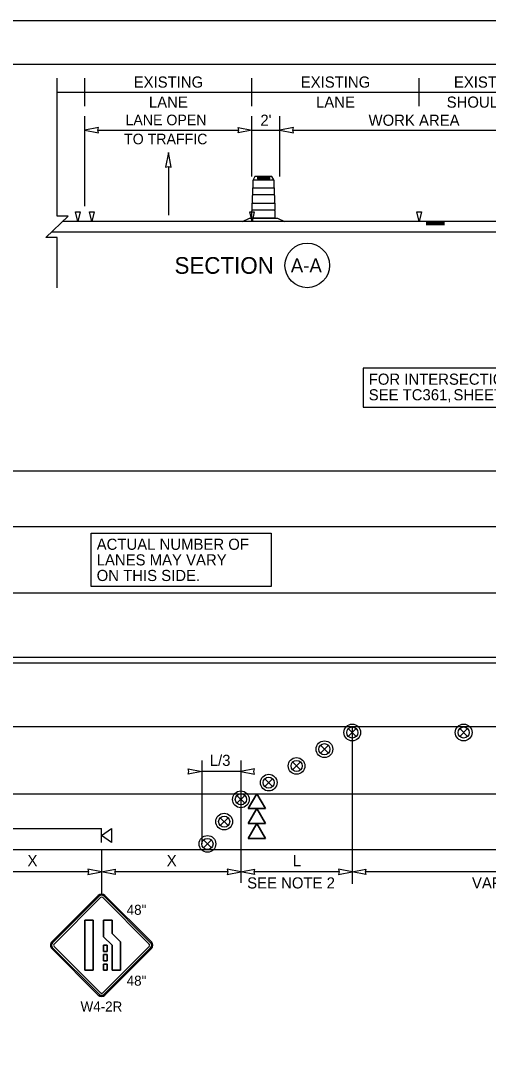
# Model space of a CAD drawing. Extents: x 99958 to 100176, y 99935 to 100011.
# Drawn here: x 100004.18 to 100007.54, y 100003.24 to 100010.69 of the extents above; entities that cross this region are included whole.
import ezdxf

# ---------------------------------------------------------------- set-up
doc = ezdxf.new("R2010")
doc.units = 0
for name, color, linetype in [('RD_ED_ShoulderPavedEdge', 7, 'Continuous'), ('RD_MK_LineDblYellowCenter', 7, 'Continuous'), ('RD_MK_LineEdgeWhite', 7, 'Continuous'), ('RD_MK_LineLane', 7, 'Continuous'), ('SH_GI_PlotLimits', 7, 'Continuous'), ('SH_GI_SheetBorder', 7, 'Continuous'), ('SH_TI_Tables', 7, 'Continuous'), ('SH_TI_WZSectionCut', 7, 'Continuous'), ('TR_SN_ConstructionSigns', 7, 'Continuous'), ('TR_WZ_ArrowLeftStrRightTurn', 7, 'Continuous'), ('TR_WZ_PortableSignMountBlk-Org', 7, 'Continuous'), ('TR_WZ_SequentialArrowSign', 7, 'Continuous'), ('TR_WZ_TrafficSafetyDrum', 7, 'Continuous'), ('TR_WZ_TrafficSafetyDrumElev', 7, 'Continuous'), ('TR_WZ_WorkZoneDetails', 7, 'Continuous'), ('TR_WZ_WorkZoneTextCurrent', 7, 'Continuous')]:
    doc.layers.add(name, color=color, linetype=linetype)

msp = doc.modelspace()

# ---------------------------------------------------------------- linework, layer by layer
at = {"layer": 'RD_ED_ShoulderPavedEdge'}
for p, q in [((100000.8283, 100007.4557), (100014.8933, 100007.4557)), ((100000.8283, 100004.7357), (100014.8933, 100004.7357))]:
    msp.add_line(p, q, dxfattribs=at)
at = {"layer": 'RD_MK_LineDblYellowCenter'}
for p, q in [((100000.8283, 100006.1157), (100014.914, 100006.1157)), ((100000.8283, 100006.0757), (100014.8726, 100006.0757))]:
    msp.add_line(p, q, dxfattribs=at)
at = {"layer": 'RD_MK_LineEdgeWhite'}
for p, q in [((100000.8283, 100007.0557), (100014.8933, 100007.0557)), ((100000.8283, 100005.1357), (100014.8933, 100005.1357))]:
    msp.add_line(p, q, dxfattribs=at)
at = {"layer": 'RD_MK_LineLane'}
for points in [[(100014.8933, 100006.5757), (100000.8283, 100006.5757)], [(100014.8933, 100005.6157), (100000.8283, 100005.6157)]]:
    msp.add_lwpolyline(points, dxfattribs=at)
at = {"layer": 'SH_GI_PlotLimits'}
msp.add_lwpolyline([(99999.0625, 99999.6875), (100016.0625, 99999.6875), (100016.0625, 100010.6875), (99999.0625, 100010.6875)], close=True, dxfattribs=at)
at = {"layer": 'SH_GI_SheetBorder'}
msp.add_line((100000, 100010.375), (100015.75, 100010.375), dxfattribs=at)
at = {"layer": 'SH_TI_Tables'}
for points in [[(100006.6416, 100007.9113), (100008.2261, 100007.9113), (100008.2261, 100008.1933), (100006.6416, 100008.1933)], [(100004.688, 100007.0077), (100005.9811, 100007.0077), (100005.9811, 100006.6241), (100004.688, 100006.6241)]]:
    msp.add_lwpolyline(points, close=True, dxfattribs=at)
at = {"layer": 'SH_TI_WZSectionCut'}
for p, q in [((100004.6434, 100010.075), (100004.6434, 100010.275)), ((100005.8434, 100010.075), (100005.8434, 100010.275)), ((100007.0434, 100010.075), (100007.0434, 100010.275)), ((100004.4434, 100010.175), (100004.6434, 100010.175)), ((100004.6434, 100010.175), (100005.8434, 100010.175)), ((100005.8434, 100010.175), (100007.0434, 100010.175)), ((100007.0434, 100010.175), (100008.0434, 100010.175)), ((100004.6434, 100009.3547), (100004.6434, 100010.001)), ((100005.8434, 100009.57), (100005.8434, 100010.001)), ((100006.0434, 100009.57), (100006.0434, 100010.001)), ((100004.7372, 100009.901), (100005.7497, 100009.901)), ((100005.8434, 100009.901), (100006.0434, 100009.901)), ((100006.1372, 100009.901), (100007.9497, 100009.901)), ((100008.0434, 100009.2449), (100004.4822, 100009.2449)), ((100007.2264, 100009.2393), (100007.0934, 100009.2393)), ((100007.2264, 100009.2337), (100007.0934, 100009.2337)), ((100007.2264, 100009.228), (100007.0934, 100009.228)), ((100007.2264, 100009.2228), (100007.0934, 100009.2228)), ((100008.0434, 100009.1699), (100004.4047, 100009.1699))]:
    msp.add_line(p, q, dxfattribs=at)
for points in [[(100004.6434, 100009.901), (100004.7417, 100009.8817), (100004.7372, 100009.901), (100004.7417, 100009.9203)], [(100005.8434, 100009.901), (100005.7451, 100009.8817), (100005.7497, 100009.901), (100005.7451, 100009.9203)], [(100006.0434, 100009.901), (100006.1417, 100009.8817), (100006.1372, 100009.901), (100006.1417, 100009.9203)], [(100004.5767, 100009.3147), (100004.6101, 100009.3147), (100004.5934, 100009.2449)], [(100004.6767, 100009.3147), (100004.7101, 100009.3147), (100004.6934, 100009.2449)], [(100005.8268, 100009.3147), (100005.8601, 100009.3147), (100005.8435, 100009.2449)], [(100007.0268, 100009.3147), (100007.0601, 100009.3147), (100007.0435, 100009.2449)]]:
    msp.add_lwpolyline(points, close=True, dxfattribs=at)
msp.add_circle((100006.24, 100008.93), 0.16, dxfattribs=at)
at = {"layer": 'TR_SN_ConstructionSigns'}
for p, q in [((100004.7397, 100004.4058), (100004.4056, 100004.0717)), ((100004.7457, 100004.3999), (100004.4116, 100004.0658)), ((100004.4215, 100004.0558), (100004.7556, 100004.3899)), ((100004.7715, 100004.3899), (100005.1056, 100004.0558)), ((100005.1156, 100004.0658), (100004.7815, 100004.3999)), ((100005.1215, 100004.0717), (100004.7874, 100004.4058)), ((100004.6419, 100004.2279), (100004.7024, 100004.2279)), ((100004.6419, 100003.8679), (100004.6419, 100004.2279)), ((100004.7024, 100004.2279), (100004.6419, 100004.2279)), ((100004.6419, 100004.2279), (100004.6419, 100003.8679)), ((100004.7024, 100004.2279), (100004.7024, 100003.8679)), ((100004.7024, 100003.8679), (100004.7024, 100004.2279)), ((100004.7776, 100004.2279), (100004.8381, 100004.2279)), ((100004.7776, 100004.1083), (100004.7776, 100004.2279)), ((100004.8381, 100004.2279), (100004.7776, 100004.2279)), ((100004.7776, 100004.2279), (100004.7776, 100004.1083)), ((100004.8381, 100004.2279), (100004.8381, 100004.1334)), ((100004.8381, 100004.1334), (100004.8381, 100004.2279)), ((100004.8381, 100004.0479), (100004.7776, 100004.1083)), ((100004.7776, 100004.1083), (100004.8381, 100004.0479)), ((100004.8381, 100004.1334), (100004.8986, 100004.0729)), ((100004.8986, 100004.0729), (100004.8381, 100004.1334)), ((100004.8986, 100004.0729), (100004.8986, 100003.8679)), ((100004.8986, 100003.8679), (100004.8986, 100004.0729)), ((100004.4056, 100004.024), (100004.7397, 100003.6899)), ((100004.4116, 100004.03), (100004.7457, 100003.6959)), ((100004.7556, 100003.7058), (100004.4215, 100004.0399)), ((100005.1056, 100004.0399), (100004.7715, 100003.7058)), ((100004.7776, 100004.0479), (100004.8044, 100004.0479)), ((100004.7776, 100004.0029), (100004.7776, 100004.0479)), ((100004.8044, 100004.0479), (100004.7776, 100004.0479)), ((100004.7776, 100004.0479), (100004.7776, 100004.0029)), ((100004.8044, 100004.0029), (100004.7776, 100004.0029)), ((100004.7776, 100004.0029), (100004.8044, 100004.0029)), ((100004.7815, 100003.6959), (100005.1156, 100004.03)), ((100004.7874, 100003.6899), (100005.1215, 100004.024)), ((100004.8044, 100004.0479), (100004.8044, 100004.0029)), ((100004.8044, 100004.0029), (100004.8044, 100004.0479)), ((100004.8381, 100003.8679), (100004.8381, 100004.0479)), ((100004.8381, 100004.0479), (100004.8381, 100003.8679)), ((100004.7776, 100003.9804), (100004.8044, 100003.9804)), ((100004.7776, 100003.9354), (100004.7776, 100003.9804)), ((100004.8044, 100003.9804), (100004.7776, 100003.9804)), ((100004.7776, 100003.9804), (100004.7776, 100003.9354)), ((100004.8044, 100003.9354), (100004.7776, 100003.9354)), ((100004.7776, 100003.9354), (100004.8044, 100003.9354)), ((100004.8044, 100003.9804), (100004.8044, 100003.9354)), ((100004.8044, 100003.9354), (100004.8044, 100003.9804)), ((100004.7024, 100003.8679), (100004.6419, 100003.8679)), ((100004.6419, 100003.8679), (100004.7024, 100003.8679)), ((100004.7776, 100003.9129), (100004.8044, 100003.9129)), ((100004.7776, 100003.8679), (100004.7776, 100003.9129)), ((100004.8044, 100003.9129), (100004.7776, 100003.9129)), ((100004.7776, 100003.9129), (100004.7776, 100003.8679)), ((100004.8044, 100003.8679), (100004.7776, 100003.8679)), ((100004.7776, 100003.8679), (100004.8044, 100003.8679)), ((100004.8044, 100003.9129), (100004.8044, 100003.8679)), ((100004.8044, 100003.8679), (100004.8044, 100003.9129)), ((100004.8986, 100003.8679), (100004.8381, 100003.8679)), ((100004.8381, 100003.8679), (100004.8986, 100003.8679))]:
    msp.add_line(p, q, dxfattribs=at)
for centre, radius, start, end in [((100004.7636, 100004.382), 0.0338, 45, 135), ((100004.7636, 100004.382), 0.0253, 45, 135), ((100004.7636, 100004.382), 0.0113, 45, 135), ((100004.4295, 100004.0479), 0.0338, 135, 225.00001), ((100005.0977, 100004.0479), 0.0338, 315.00001, 45.00001), ((100004.4295, 100004.0479), 0.0253, 135, 225.00001), ((100004.4295, 100004.0479), 0.0113, 135, 225.00001), ((100005.0977, 100004.0479), 0.0113, 315.00002, 45), ((100005.0977, 100004.0479), 0.0253, 315.00002, 45), ((100004.7636, 100003.7138), 0.0113, 225.00001, 315.00002), ((100004.7636, 100003.7138), 0.0338, 225.00001, 315.00001), ((100004.7636, 100003.7138), 0.0253, 225.00001, 315.00002)]:
    msp.add_arc(centre, radius, start, end, dxfattribs=at)
at = {"layer": 'TR_WZ_ArrowLeftStrRightTurn'}
msp.add_line((100005.2434, 100009.6418), (100005.2434, 100009.292), dxfattribs=at)
msp.add_lwpolyline([(100005.2434, 100009.742), (100005.2228, 100009.6369), (100005.2434, 100009.6418), (100005.264, 100009.6369)], close=True, dxfattribs=at)
at = {"layer": 'TR_WZ_PortableSignMountBlk-Org'}
msp.add_line((100004.7636, 100004.7858), (100004.7636, 100004.8858), dxfattribs=at)
msp.add_lwpolyline([(100004.7636, 100004.8357), (100004.8354, 100004.8858), (100004.8354, 100004.7858)], close=True, dxfattribs=at)
at = {"layer": 'TR_WZ_SequentialArrowSign'}
for points in [[(100005.8778, 100005.1357), (100005.8161, 100005.0291), (100005.8778, 100005.0291), (100005.9396, 100005.0291), (100005.8778, 100005.1357)], [(100005.9396, 100005.0291), (100005.8778, 100005.0291), (100005.8161, 100005.0291), (100005.8778, 100005.1357), (100005.9396, 100005.0291)], [(100005.8778, 100005.0291), (100005.8161, 100004.9224), (100005.8778, 100004.9224), (100005.9396, 100004.9224), (100005.8778, 100005.0291)], [(100005.9396, 100004.9224), (100005.8778, 100004.9224), (100005.8161, 100004.9224), (100005.8778, 100005.0291), (100005.9396, 100004.9224)], [(100005.8778, 100004.9224), (100005.8161, 100004.8157), (100005.9396, 100004.8157), (100005.8778, 100004.9224)], [(100005.9396, 100004.8157), (100005.8161, 100004.8157), (100005.8778, 100004.9224), (100005.9396, 100004.8157)]]:
    msp.add_lwpolyline(points, dxfattribs=at)
at = {"layer": 'TR_WZ_TrafficSafetyDrum'}
for p, q in [((100006.5353, 100005.604), (100006.5919, 100005.5474)), ((100006.5919, 100005.604), (100006.5353, 100005.5474)), ((100007.3353, 100005.604), (100007.3919, 100005.5474)), ((100007.3919, 100005.604), (100007.3353, 100005.5474)), ((100006.3353, 100005.484), (100006.3919, 100005.4274)), ((100006.3919, 100005.484), (100006.3353, 100005.4274)), ((100006.1353, 100005.364), (100006.1919, 100005.3074)), ((100006.1919, 100005.364), (100006.1353, 100005.3074)), ((100005.9353, 100005.244), (100005.9919, 100005.1874)), ((100005.9919, 100005.244), (100005.9353, 100005.1874)), ((100005.7353, 100005.124), (100005.7919, 100005.0674)), ((100005.7919, 100005.124), (100005.7353, 100005.0674)), ((100005.6153, 100004.964), (100005.6719, 100004.9074)), ((100005.6719, 100004.964), (100005.6153, 100004.9074)), ((100005.4953, 100004.804), (100005.5519, 100004.7474)), ((100005.5519, 100004.804), (100005.4953, 100004.7474))]:
    msp.add_line(p, q, dxfattribs=at)
for centre, radius in [((100006.5636, 100005.5757), 0.06), ((100006.5636, 100005.5757), 0.06), ((100007.3636, 100005.5757), 0.06), ((100007.3636, 100005.5757), 0.06), ((100006.5636, 100005.5757), 0.04), ((100007.3636, 100005.5757), 0.04), ((100006.3636, 100005.4557), 0.06), ((100006.3636, 100005.4557), 0.06), ((100006.3636, 100005.4557), 0.04), ((100006.1636, 100005.3357), 0.06), ((100006.1636, 100005.3357), 0.06), ((100006.1636, 100005.3357), 0.04), ((100005.9636, 100005.2157), 0.06), ((100005.9636, 100005.2157), 0.06), ((100005.9636, 100005.2157), 0.04), ((100005.7636, 100005.0957), 0.06), ((100005.7636, 100005.0957), 0.06), ((100005.7636, 100005.0957), 0.04), ((100005.6436, 100004.9357), 0.06), ((100005.6436, 100004.9357), 0.06), ((100005.6436, 100004.9357), 0.04), ((100005.5236, 100004.7757), 0.06), ((100005.5236, 100004.7757), 0.06), ((100005.5236, 100004.7757), 0.04)]:
    msp.add_circle(centre, radius, dxfattribs=at)
at = {"layer": 'TR_WZ_TrafficSafetyDrumElev'}
for p, q in [((100005.8518, 100009.545), (100005.9998, 100009.545)), ((100005.8518, 100009.545), (100005.9998, 100009.545)), ((100005.8863, 100009.564), (100005.9681, 100009.564)), ((100005.9681, 100009.551), (100005.8863, 100009.551)), ((100005.849, 100009.4871), (100006.0027, 100009.4871)), ((100005.849, 100009.4372), (100005.849, 100009.4871)), ((100006.0027, 100009.4372), (100005.849, 100009.4372)), ((100006.0027, 100009.4871), (100006.0027, 100009.4372)), ((100005.8453, 100009.377), (100006.0064, 100009.377)), ((100005.8453, 100009.3271), (100005.8453, 100009.377)), ((100006.0064, 100009.377), (100006.0064, 100009.3271)), ((100006.0064, 100009.3271), (100005.8453, 100009.3271))]:
    msp.add_line(p, q, dxfattribs=at)
for points in [[(100005.8508, 100009.4915), (100005.8508, 100009.543)], [(100005.8508, 100009.4915), (100005.8508, 100009.543)], [(100006.0008, 100009.543), (100006.0008, 100009.4915)], [(100006.0008, 100009.543), (100006.0008, 100009.4915)], [(100005.8471, 100009.3814), (100005.8471, 100009.4327)], [(100005.8471, 100009.3814), (100005.8471, 100009.4327)], [(100005.849, 100009.4365), (100005.849, 100009.4878)], [(100005.849, 100009.4365), (100005.849, 100009.4878)], [(100006.0027, 100009.4878), (100006.0027, 100009.4365)], [(100006.0027, 100009.4878), (100006.0027, 100009.4365)], [(100006.0045, 100009.4327), (100006.0045, 100009.3814)], [(100006.0045, 100009.4327), (100006.0045, 100009.3814)], [(100005.8453, 100009.3264), (100005.8453, 100009.3777)], [(100005.8453, 100009.3264), (100005.8453, 100009.3777)], [(100006.0064, 100009.3777), (100006.0064, 100009.3264)], [(100006.0064, 100009.3777), (100006.0064, 100009.3264)], [(100006.0082, 100009.3226), (100006.0082, 100009.27), (100005.8434, 100009.27), (100005.8434, 100009.3226)], [(100006.0082, 100009.3226), (100006.0082, 100009.27), (100005.8434, 100009.27), (100005.8434, 100009.3226)]]:
    msp.add_lwpolyline(points, dxfattribs=at)
for points in [[(100005.9998, 100009.545), (100005.9867, 100009.57), (100005.865, 100009.57), (100005.8518, 100009.545)], [(100005.7758, 100009.245), (100005.8261, 100009.27), (100006.0256, 100009.27), (100006.0758, 100009.245)]]:
    msp.add_lwpolyline(points, close=True, dxfattribs=at)
for centre, major_axis, ratio, start_param, end_param in [((100005.852, 100009.5426), (0, 0.00249), 0.493438, 0.177149, 1.393647), ((100005.852, 100009.5426), (0, 0.00249), 0.493438, 0.177149, 1.393647), ((100005.8863, 100009.5575), (0, 0.0065), 0.570305, 0, 3.141593), ((100005.9681, 100009.5575), (0, 0.0065), 0.570305, 3.141593, 6.283185), ((100005.9996, 100009.5426), (0, 0.00249), 0.493438, 4.889538, 6.106036), ((100005.9996, 100009.5426), (0, 0.00249), 0.493438, 4.889538, 6.106036), ((100005.8505, 100009.4296), (0, 0.00758), 0.493438, 0.4288, 1.141997), ((100005.8505, 100009.4296), (0, 0.00758), 0.493438, 0.4288, 1.141997), ((100005.8524, 100009.4846), (0, 0.00758), 0.493438, 0.4288, 1.141997), ((100005.8524, 100009.4846), (0, 0.00758), 0.493438, 0.4288, 1.141997), ((100005.9993, 100009.4846), (0, 0.00758), 0.493438, 5.141189, 5.854386), ((100005.9993, 100009.4846), (0, 0.00758), 0.493438, 5.141189, 5.854386), ((100006.0011, 100009.4296), (0, 0.00758), 0.493438, 5.141189, 5.854386), ((100006.0011, 100009.4296), (0, 0.00758), 0.493438, 5.141189, 5.854386), ((100005.8487, 100009.3745), (0, 0.00758), 0.493438, 0.4288, 1.141997), ((100005.8487, 100009.3745), (0, 0.00758), 0.493438, 0.4288, 1.141997), ((100006.003, 100009.3745), (0, 0.00758), 0.493438, 5.141189, 5.854386), ((100006.003, 100009.3745), (0, 0.00758), 0.493438, 5.141189, 5.854386), ((100005.8468, 100009.3195), (0, 0.00758), 0.493438, 0.4288, 1.141997), ((100005.8468, 100009.3195), (0, 0.00758), 0.493438, 0.4288, 1.141997), ((100006.0048, 100009.3195), (0, 0.00758), 0.493438, 5.141189, 5.854386), ((100006.0048, 100009.3195), (0, 0.00758), 0.493438, 5.141189, 5.854386)]:
    msp.add_ellipse(centre, major_axis=major_axis, ratio=ratio, start_param=start_param, end_param=end_param, dxfattribs=at)
at = {"layer": 'TR_WZ_WorkZoneDetails'}
for p, q in [((100006.5636, 100005.6157), (100006.5636, 100004.4891)), ((100005.4836, 100005.3757), (100005.4836, 100004.7757)), ((100005.7636, 100005.3757), (100005.7636, 100004.4957)), ((100005.7636, 100005.2957), (100005.4836, 100005.2957)), ((100002.1636, 100004.8858), (100004.7636, 100004.8858)), ((100004.7636, 100004.736), (100004.7636, 100004.4157)), ((100004.6698, 100004.5757), (100003.8573, 100004.5757)), ((100005.6698, 100004.5757), (100004.8573, 100004.5757)), ((100006.4698, 100004.5757), (100005.8573, 100004.5757)), ((100009.4699, 100004.5757), (100006.6573, 100004.5757))]:
    msp.add_line(p, q, dxfattribs=at)
msp.add_lwpolyline([(100004.4434, 100008.7701), (100004.4434, 100009.13), (100004.3634, 100009.13), (100004.5235, 100009.2849), (100004.4434, 100009.2849), (100004.4434, 100010.275)], dxfattribs=at)
for points in [[(100005.4836, 100005.2957), (100005.3853, 100005.2765), (100005.3898, 100005.2957), (100005.3853, 100005.315)], [(100005.7636, 100005.2957), (100005.8619, 100005.2765), (100005.8573, 100005.2957), (100005.8619, 100005.315)], [(100004.7636, 100004.5757), (100004.6653, 100004.595), (100004.6698, 100004.5757), (100004.6653, 100004.5565)], [(100004.7636, 100004.5757), (100004.8619, 100004.595), (100004.8573, 100004.5757), (100004.8619, 100004.5565)], [(100005.7636, 100004.5757), (100005.6653, 100004.595), (100005.6698, 100004.5757), (100005.6653, 100004.5565)], [(100005.7636, 100004.5757), (100005.8619, 100004.595), (100005.8573, 100004.5757), (100005.8619, 100004.5565)], [(100006.5636, 100004.5757), (100006.4653, 100004.595), (100006.4698, 100004.5757), (100006.4653, 100004.5565)], [(100006.5636, 100004.5757), (100006.6619, 100004.595), (100006.6573, 100004.5757), (100006.6619, 100004.5565)]]:
    msp.add_lwpolyline(points, close=True, dxfattribs=at)

# ---------------------------------------------------------------- texts
at = {"layer": 'SH_TI_Tables'}
for s, p in [('FOR INTERSECTION DETAILS: ', (100006.6816, 100008.0733)), ('SEE TC361, ', (100006.6816, 100007.9613)), ('SHEET 2A', (100007.2903, 100007.9613))]:
    msp.add_text(s, height=0.08, dxfattribs=at).set_placement(p)
for s, p in [('ACTUAL NUMBER OF', (100004.728, 100006.8877)), ('LANES MAY VARY', (100004.728, 100006.7757)), ('ON THIS SIDE.', (100004.728, 100006.6637))]:
    msp.add_text(s, height=0.08, rotation=360, dxfattribs=at).set_placement(p)
at = {"layer": 'SH_TI_WZSectionCut'}
for s, height, p in [('EXISTING', 0.08, (100004.9936, 100010.207)), ('EXISTING', 0.08, (100006.1936, 100010.207)), ('EXISTING', 0.08, (100007.2936, 100010.207)), ('LANE', 0.08, (100005.103, 100010.063)), ('LANE', 0.08, (100006.303, 100010.063)), ('SHOULDER', 0.08, (100007.2417, 100010.063)), ('SECTION', 0.12, (100005.2869, 100008.87)), ('A-A', 0.1, (100006.1221, 100008.88))]:
    msp.add_text(s, height=height, rotation=360, dxfattribs=at).set_placement(p)
for s, height, p in [('LANE OPEN', 0.076, (100004.9348, 100009.937)), ("2'", 0.08, (100005.9034, 100009.933)), ('WORK AREA', 0.08, (100006.6805, 100009.933)), ('TO TRAFFIC', 0.076, (100004.9247, 100009.8002))]:
    msp.add_text(s, height=height, dxfattribs=at).set_placement(p)
at = {"layer": 'TR_SN_ConstructionSigns'}
for s, p in [('48"', (100004.9434, 100004.2664)), ('48"', (100004.9434, 100003.7573)), ('W4-2R', (100004.6121, 100003.572))]:
    msp.add_text(s, height=0.072, rotation=360, dxfattribs=at).set_placement(p)
at = {"layer": 'TR_WZ_WorkZoneTextCurrent'}
msp.add_text('L/3', height=0.08, dxfattribs=at).set_placement((100005.5403, 100005.3357))
for s, p in [('X', (100004.2311, 100004.6157)), ('X', (100005.2311, 100004.6157)), ('L', (100006.1364, 100004.6157)), ('SEE NOTE 2', (100005.8088, 100004.4557)), ('VARIES, SEE NOTE 3', (100007.4234, 100004.4557))]:
    msp.add_text(s, height=0.08, rotation=360, dxfattribs=at).set_placement(p)

doc.saveas('drawing.dxf')
